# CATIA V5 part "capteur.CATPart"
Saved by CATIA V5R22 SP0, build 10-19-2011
Part number: Part23
Bounding box of the stored display mesh (mm): x 0 to 10, y 0 to 10, z 0 to 15
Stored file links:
  C:\Users\La forge\Desktop\CAO_PER_pick&place_2023A\Sous_Ensemble_Flacon\Verin\capteur.CATPart
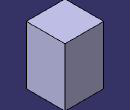
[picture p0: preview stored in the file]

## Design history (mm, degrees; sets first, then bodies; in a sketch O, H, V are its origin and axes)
Body1 (main body)
  Sketch1 on yz-plane, origin (0, 0, 0), H (0, 1, 0), V (0, 0, 1)
    line L1 (0, 0) -> (10, 0)
    line L2 (10, 0) -> (10, 15)
    line L3 (10, 15) -> (0, 15)
    line L4 (0, 15) -> (0, 0)
    point P1 (10, 0)
    point P2 (10, 15)
    point P3 (0, 15)
    distance P2 P3 = 10
    distance P2 P1 = 15
    horizontal: L1 H, L3 H
    vertical: L2 V, L4 V
  Pad1: profile Sketch1, direction (1, 0, 0), length 10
